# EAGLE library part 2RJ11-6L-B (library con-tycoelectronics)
CORCOM Modular RJ Jacks L - Ganged Series Source: www.tycoelectronics.com .. ENG_DS_1654001_1099_RJ_L_0507.pdf
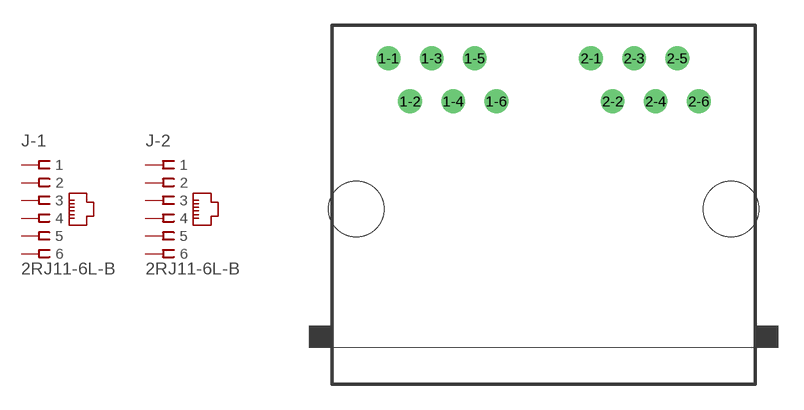
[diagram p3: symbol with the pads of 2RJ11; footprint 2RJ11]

Designator prefix J; gates -1=JACK6 -2=JACK6

## 2RJ11-6L-B (MF: TYCO ELECTRONICS; MPN: 2RJ11-6L-B; OC_FARNELL: unknown; OC_NEWARK: 48F3954)  [2RJ11]
1-1  -1:1  pas
1-2  -1:2  pas
1-3  -1:3  pas
1-4  -1:4  pas
1-5  -1:5  pas
1-6  -1:6  pas
2-1  -2:1  pas
2-2  -2:2  pas
2-3  -2:3  pas
2-4  -2:4  pas
2-5  -2:5  pas
2-6  -2:6  pas

## Footprint 2RJ11 (pad centres in mm)
RJ11 x 2 Source: www.tycoelectronics.com .. ENG_DS_1654001_1099_RJ_L_0507.pdf
drill 0.9 pad 1.4 round: 1-1 -9.144,8.89; 1-2 -7.874,6.35; 1-3 -6.604,8.89; 1-4 -5.334,6.35; 1-5 -4.064,8.89; 1-6 -2.794,6.35; 2-1 2.794,8.89; 2-2 4.064,6.35; 2-3 5.334,8.89; 2-4 6.604,6.35; 2-5 7.874,8.89; 2-6 9.144,6.35
hole 3.251 at -11.049,0
hole 3.251 at 11.049,0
